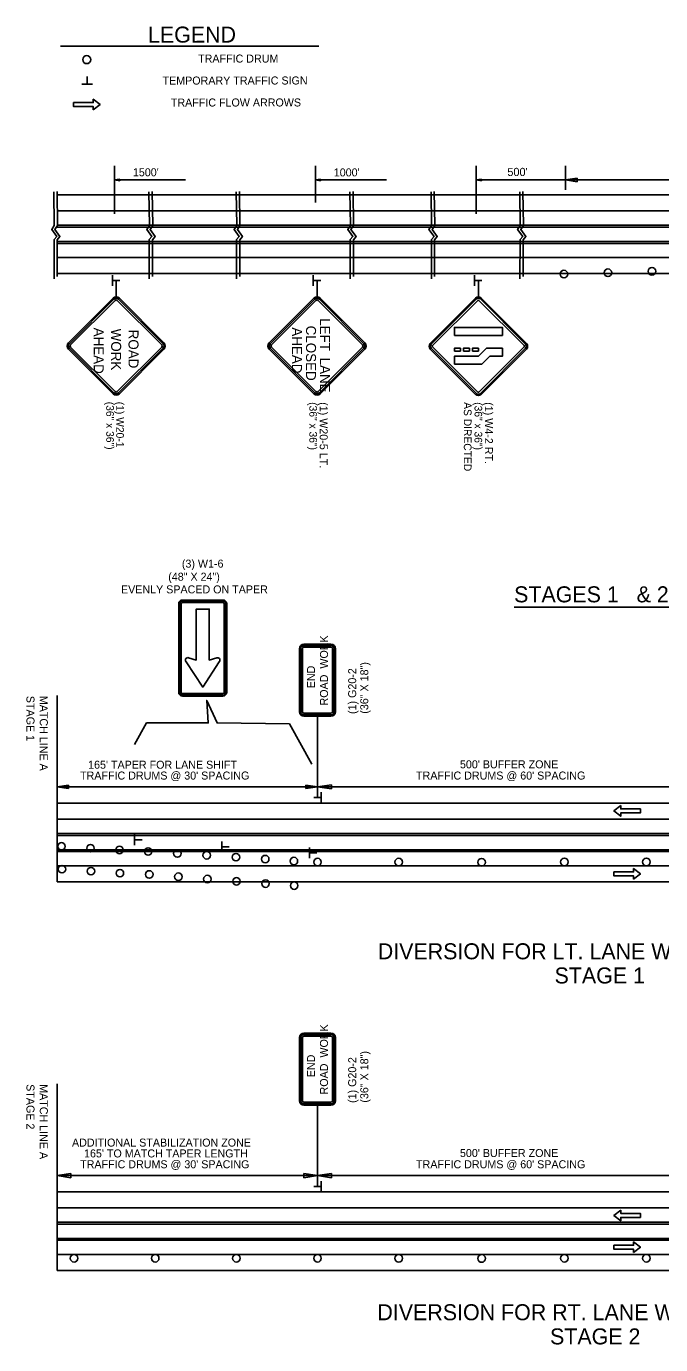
# Model space of a CAD drawing. Extents: x 1930579 to 1938445, y 596452 to 597630.
# Drawn here: x 1936470 to 1936946, y 596628 to 597617 of the extents above; entities that cross this region are included whole.
import ezdxf

# ---------------------------------------------------------------- set-up
doc = ezdxf.new("R2010")
doc.units = 0
for name, color, linetype in [('Default', 7, 'Continuous'), ('P_TC_Signs_Permanent', 7, 'Continuous'), ('P_TC_Signs_Temporary', 7, 'Continuous'), ('R_Border', 7, 'Continuous'), ('R_MOT', 7, 'Continuous'), ('R_Striping', 7, 'Continuous')]:
    doc.layers.add(name, color=color, linetype=linetype)

msp = doc.modelspace()

# ---------------------------------------------------------------- linework, layer by layer
at = {"layer": 'Default'}
for p, q in [((1936536.26, 597511.96), (1936536.26, 597476.04)), ((1936686.9, 597511.96), (1936686.9, 597484.57)), ((1936807.47, 597511.96), (1936807.47, 597476.04)), ((1936874.25, 597511.96), (1936874.25, 597493.95)), ((1936540.09, 597502), (1936536.26, 597501.43)), ((1936536.26, 597501.43), (1936589.49, 597501.43)), ((1936540.09, 597500.85), (1936536.26, 597501.43)), ((1936540.09, 597501.91), (1936536.9, 597501.43)), ((1936540.09, 597500.95), (1936536.9, 597501.43)), ((1936540.09, 597501.81), (1936537.56, 597501.43)), ((1936540.09, 597501.05), (1936537.56, 597501.43)), ((1936540.09, 597501.71), (1936538.2, 597501.43)), ((1936540.09, 597501.14), (1936538.2, 597501.43)), ((1936540.09, 597501.62), (1936538.84, 597501.43)), ((1936540.09, 597501.24), (1936538.84, 597501.43)), ((1936540.09, 597501.52), (1936539.48, 597501.43)), ((1936540.09, 597501.34), (1936539.48, 597501.43)), ((1936540.09, 597500.85), (1936540.09, 597502)), ((1936690.72, 597502), (1936686.9, 597501.43)), ((1936686.9, 597501.43), (1936740.13, 597501.43)), ((1936690.72, 597500.85), (1936686.9, 597501.43)), ((1936690.72, 597501.91), (1936687.54, 597501.43)), ((1936690.72, 597500.95), (1936687.54, 597501.43)), ((1936690.72, 597501.81), (1936688.2, 597501.43)), ((1936690.72, 597501.05), (1936688.2, 597501.43)), ((1936690.72, 597501.71), (1936688.83, 597501.43)), ((1936690.72, 597501.14), (1936688.83, 597501.43)), ((1936690.72, 597501.62), (1936689.48, 597501.43)), ((1936690.72, 597501.24), (1936689.48, 597501.43)), ((1936690.72, 597501.52), (1936690.12, 597501.43)), ((1936690.72, 597501.34), (1936690.12, 597501.43)), ((1936690.72, 597500.85), (1936690.72, 597502)), ((1936811.29, 597502), (1936807.47, 597501.43)), ((1936807.47, 597501.43), (1936874.25, 597501.43)), ((1936811.29, 597500.85), (1936807.47, 597501.43)), ((1936811.29, 597501.91), (1936808.1, 597501.43)), ((1936811.29, 597500.95), (1936808.1, 597501.43)), ((1936811.29, 597501.81), (1936808.76, 597501.43)), ((1936811.29, 597501.05), (1936808.76, 597501.43)), ((1936811.29, 597501.71), (1936809.4, 597501.43)), ((1936811.29, 597501.14), (1936809.4, 597501.43)), ((1936811.29, 597501.62), (1936810.05, 597501.43)), ((1936811.29, 597501.24), (1936810.05, 597501.43)), ((1936811.29, 597501.52), (1936810.69, 597501.43)), ((1936811.29, 597501.34), (1936810.69, 597501.43)), ((1936811.29, 597500.85), (1936811.29, 597502)), ((1936874.25, 597501.43), (1936883.11, 597502.76)), ((1937241.46, 597501.43), (1936874.25, 597501.43)), ((1936883.11, 597500.1), (1936874.25, 597501.43)), ((1936883.11, 597502.76), (1936883.11, 597500.1)), ((1937493.2, 597490.19), (1936493.11, 597490.19)), ((1937493.2, 597478.19), (1936493.3, 597478.19)), ((1937493.2, 597466.02), (1936492.72, 597466.02)), ((1937493.2, 597467.4), (1936493.46, 597467.4)), ((1937493.2, 597455.23), (1936493.31, 597455.23)), ((1937493.2, 597453.85), (1936493.31, 597453.85)), ((1937493.2, 597443.19), (1936493.31, 597443.19)), ((1937493.2, 597431.19), (1936493.31, 597431.19)), ((1936534.64, 597422.09), (1936534.64, 597430.07)), ((1936534.76, 597426.06), (1936540.21, 597426.06)), ((1936685.22, 597422.09), (1936685.22, 597430.07)), ((1936685.34, 597426.06), (1936690.79, 597426.06)), ((1936806.18, 597422.09), (1936806.18, 597430.07)), ((1936806.3, 597426.05), (1936811.75, 597426.05)), ((1936835.84, 597181.22), (1936964.15, 597181.22)), ((1936493.11, 597114.97), (1936493.11, 596975.31)), ((1936493.11, 597046.45), (1936501.81, 597047.75)), ((1936688.44, 597046.45), (1936493.11, 597046.45)), ((1936501.81, 597045.15), (1936493.11, 597046.45)), ((1936501.81, 597047.75), (1936501.81, 597045.15)), ((1936679.75, 597045.15), (1936679.75, 597047.75)), ((1936679.75, 597047.75), (1936688.44, 597046.45)), ((1936688.44, 597046.45), (1936679.75, 597045.15)), ((1936691.12, 597038.47), (1936685.67, 597038.47)), ((1936997.05, 597046.45), (1936688.44, 597046.45)), ((1936688.53, 597046.45), (1936698.83, 597048)), ((1936698.83, 597044.9), (1936688.53, 597046.45)), ((1936691.23, 597042.43), (1936691.23, 597034.45)), ((1936698.83, 597048), (1936698.83, 597044.9)), ((1937498.74, 597034.31), (1936493.11, 597034.31)), ((1936493.11, 597022.31), (1937498.74, 597022.31)), ((1937498.74, 597011.52), (1936493.11, 597011.52)), ((1937498.74, 597010.14), (1936493.11, 597010.14)), ((1936551.31, 597002.87), (1936551.31, 597010.85)), ((1937498.74, 596999.34), (1936493.11, 596999.34)), ((1936551.43, 597006.84), (1936556.87, 597006.84)), ((1936616.72, 596997.46), (1936616.72, 597005.44)), ((1936616.84, 597001.42), (1936622.29, 597001.42)), ((1936682.29, 596992.94), (1936682.29, 597000.92)), ((1937498.74, 596998.03), (1936493.11, 596998.03)), ((1936682.4, 596996.91), (1936687.85, 596996.91)), ((1936493.11, 596987.31), (1937498.74, 596987.31)), ((1936493.11, 596975.31), (1936773.63, 596975.31)), ((1937498.74, 596975.31), (1936493.11, 596975.31)), ((1936757.75, 596975.31), (1937032.82, 596975.31)), ((1936493.11, 596823.85), (1936493.11, 596683.94)), ((1936688.44, 596765.87), (1936688.44, 596749.76)), ((1936493.11, 596755.08), (1936503.42, 596756.63)), ((1936688.53, 596755.08), (1936493.11, 596755.08)), ((1936503.42, 596753.53), (1936493.11, 596755.08)), ((1936503.42, 596756.63), (1936503.42, 596753.53)), ((1936678.23, 596753.53), (1936678.23, 596756.63)), ((1936678.23, 596756.63), (1936688.53, 596755.08)), ((1936688.53, 596755.08), (1936678.23, 596753.53)), ((1936997.05, 596755.08), (1936688.44, 596755.08)), ((1936688.53, 596755.08), (1936698.83, 596756.63)), ((1936698.83, 596753.53), (1936688.53, 596755.08)), ((1936698.83, 596756.63), (1936698.83, 596753.53)), ((1937498.74, 596742.94), (1936493.11, 596742.94)), ((1936691.12, 596746.92), (1936685.67, 596746.92)), ((1936691.23, 596750.89), (1936691.23, 596742.91)), ((1936493.11, 596730.94), (1937498.74, 596730.94)), ((1937498.74, 596720.15), (1936493.11, 596720.15)), ((1937498.74, 596718.77), (1936493.11, 596718.77)), ((1937498.74, 596707.98), (1936493.11, 596707.98)), ((1937498.74, 596706.66), (1936493.11, 596706.66)), ((1936493.11, 596695.94), (1937498.74, 596695.94)), ((1937498.74, 596683.94), (1936493.11, 596683.94)), ((1936688.44, 596683.94), (1936773.63, 596683.94)), ((1936757.75, 596683.94), (1937032.82, 596683.94))]:
    msp.add_line(p, q, dxfattribs=at)
for points in [[(1936490.68, 597492.48), (1936491.07, 597467.24), (1936489.12, 597464.34), (1936492.91, 597459.14), (1936490.92, 597456.74), (1936490.91, 597427.4)], [(1936493.08, 597492.71), (1936493.46, 597467.14), (1936491.52, 597464.24), (1936495.31, 597459.04), (1936493.31, 597456.64), (1936493.31, 597429.08)], [(1936562.05, 597492.48), (1936562.43, 597467.24), (1936560.48, 597464.34), (1936564.28, 597459.14), (1936562.28, 597456.74), (1936562.27, 597427.4)], [(1936564.44, 597492.71), (1936564.83, 597467.14), (1936562.88, 597464.24), (1936566.68, 597459.04), (1936564.68, 597456.64), (1936564.67, 597429.08)], [(1936627.49, 597492.48), (1936627.87, 597467.24), (1936625.92, 597464.34), (1936629.72, 597459.14), (1936627.72, 597456.74), (1936627.72, 597427.4)], [(1936629.88, 597492.71), (1936630.27, 597467.14), (1936628.32, 597464.24), (1936632.12, 597459.04), (1936630.12, 597456.64), (1936630.12, 597429.08)], [(1936712.68, 597492.48), (1936713.07, 597467.24), (1936711.12, 597464.34), (1936714.91, 597459.14), (1936712.92, 597456.74), (1936712.91, 597427.4)], [(1936715.08, 597492.71), (1936715.46, 597467.14), (1936713.52, 597464.24), (1936717.31, 597459.04), (1936715.31, 597456.64), (1936715.31, 597429.08)], [(1936773.57, 597492.48), (1936773.95, 597467.24), (1936772, 597464.34), (1936775.8, 597459.14), (1936773.8, 597456.74), (1936773.79, 597427.4)], [(1936775.96, 597492.71), (1936776.35, 597467.14), (1936774.4, 597464.24), (1936778.2, 597459.04), (1936776.2, 597456.64), (1936776.19, 597429.08)], [(1936840.02, 597492.48), (1936840.41, 597467.24), (1936838.46, 597464.34), (1936842.26, 597459.14), (1936840.26, 597456.74), (1936840.25, 597427.4)], [(1936842.42, 597492.71), (1936842.8, 597467.14), (1936840.86, 597464.24), (1936844.65, 597459.04), (1936842.65, 597456.64), (1936842.65, 597429.08)]]:
    msp.add_lwpolyline(points, dxfattribs=at)
for centre, radius in [((1936515.36, 597591.57), 3), ((1936873.17, 597430.82), 2.87), ((1936906.15, 597431.86), 2.87), ((1936939.14, 597432.91), 2.87), ((1936496.43, 597001.89), 2.81), ((1936518.18, 597000.54), 2.81), ((1936539.92, 596999.19), 2.81), ((1936561.41, 596998), 2.81), ((1936583.36, 596996.58), 2.81), ((1936605.32, 596995.17), 2.81), ((1936627.27, 596993.75), 2.81), ((1936649.22, 596992.34), 2.81), ((1936670.72, 596990.86), 2.81), ((1936688.44, 596990.1), 2.81), ((1936749.3, 596990.1), 2.87), ((1936811.44, 596989.95), 2.87), ((1936873.58, 596990.16), 2.87), ((1936935.06, 596990.17), 2.87), ((1936496.8, 596984.78), 2.81), ((1936518.53, 596983.27), 2.81), ((1936540.25, 596981.76), 2.81), ((1936562.28, 596980.82), 2.81), ((1936584.07, 596979.1), 2.81), ((1936605.86, 596977.39), 2.81), ((1936627.65, 596975.67), 2.81), ((1936649.45, 596973.95), 2.81), ((1936670.92, 596972.45), 2.81), ((1936505.88, 596693.1), 2.81), ((1936566.73, 596693.1), 2.81), ((1936627.59, 596693.1), 2.81), ((1936688.44, 596693.1), 2.81), ((1936749.3, 596693.1), 2.87), ((1936811.44, 596692.96), 2.87), ((1936873.58, 596693.16), 2.87), ((1936935.06, 596693.18), 2.87)]:
    msp.add_circle(centre, radius, dxfattribs=at)
at = {"layer": 'P_TC_Signs_Permanent'}
for p, q in [((1936772.96, 597378.89), (1936806.9, 597412.83)), ((1936827.02, 597384.81), (1936827.02, 597390.81)), ((1936806.9, 597340.7), (1936772.96, 597374.65)), ((1936845.09, 597374.65), (1936811.15, 597340.7)), ((1936584.33, 597183.71), (1936584.33, 597117.33)), ((1936585.08, 597183.71), (1936585.08, 597117.33)), ((1936586.2, 597183.71), (1936586.2, 597117.33)), ((1936617.51, 597186.52), (1936587.14, 597186.52)), ((1936617.51, 597185.77), (1936587.14, 597185.77)), ((1936617.51, 597184.65), (1936587.14, 597184.65)), ((1936618.45, 597117.33), (1936618.45, 597183.71)), ((1936619.58, 597117.33), (1936619.58, 597183.71)), ((1936620.33, 597117.33), (1936620.33, 597183.71)), ((1936587.14, 597116.4), (1936617.51, 597116.4)), ((1936587.14, 597115.27), (1936617.51, 597115.27)), ((1936587.14, 597114.52), (1936617.51, 597114.52))]:
    msp.add_line(p, q, dxfattribs=at)
for points in [[(1936807.54, 597412.19), (1936773.6, 597378.25)], [(1936774.66, 597377.19), (1936808.6, 597411.13)], [(1936809.45, 597411.13), (1936843.39, 597377.19)], [(1936844.45, 597378.25), (1936810.51, 597412.19)], [(1936811.15, 597412.83), (1936828.12, 597395.86), (1936845.09, 597378.89)], [(1936773.6, 597375.28), (1936807.54, 597341.34)], [(1936808.6, 597342.4), (1936774.66, 597376.34)], [(1936843.39, 597376.34), (1936809.45, 597342.4)], [(1936810.51, 597341.34), (1936844.45, 597375.28)], [(1936612.96, 597143.22), (1936607.2, 597141.5), (1936607.2, 597179.77), (1936597.45, 597179.77), (1936597.45, 597141.5), (1936591.7, 597143.26)], [(1936589.88, 597140.26), (1936602.33, 597121.27), (1936614.73, 597140.27)]]:
    msp.add_lwpolyline(points, dxfattribs=at)
for points in [[(1936791.02, 597384.81), (1936791.02, 597390.81), (1936827.02, 597390.81), (1936827.02, 597384.81)], [(1936791.02, 597373.17), (1936791.02, 597375.27), (1936795.52, 597375.27), (1936795.52, 597373.17)], [(1936791.02, 597363.27), (1936791.02, 597369.27), (1936809.02, 597369.27), (1936815.02, 597375.27), (1936827.02, 597375.27), (1936827.02, 597369.27), (1936817.51, 597369.27), (1936811.51, 597363.27)], [(1936797.77, 597373.17), (1936797.77, 597375.27), (1936802.27, 597375.27), (1936802.27, 597373.17)], [(1936804.52, 597373.17), (1936804.52, 597375.27), (1936809.02, 597375.27), (1936809.02, 597373.17)]]:
    msp.add_lwpolyline(points, close=True, dxfattribs=at)
for centre, radius, start, end in [((1936809.02, 597410.71), 3, 45, 135), ((1936809.02, 597410.71), 2.1, 45, 135), ((1936809.02, 597410.71), 0.6, 45, 135), ((1936775.08, 597376.77), 3, 135, 225), ((1936775.08, 597376.77), 2.1, 135, 225), ((1936775.08, 597376.77), 0.6, 135, 225), ((1936842.97, 597376.77), 0.6, 315, 45), ((1936842.97, 597376.77), 2.1, 315, 45), ((1936842.97, 597376.77), 3, 315, 45), ((1936809.02, 597342.83), 3, 225, 315), ((1936809.02, 597342.83), 2.1, 225, 315), ((1936809.02, 597342.83), 0.6, 225, 315), ((1936587.14, 597183.71), 2.81, 90, 180), ((1936587.14, 597183.71), 2.06, 90, 180), ((1936587.14, 597183.71), 0.938, 90, 180), ((1936617.51, 597183.71), 2.81, 360, 90), ((1936617.51, 597183.71), 2.06, 360, 90), ((1936617.51, 597183.71), 0.937, 360, 90), ((1936591.21, 597141.53), 1.8, 74.03093, 213.47548), ((1936527.15, 597099.16), 75, 33.2286, 33.47548), ((1936613.44, 597141.53), 1.76, 326.59943, 105.96908), ((1936677.53, 597099.27), 75, 146.59943, 146.85697), ((1936587.14, 597117.33), 2.81, 180, 270), ((1936587.14, 597117.33), 2.06, 180, 270), ((1936587.14, 597117.33), 0.938, 180, 270), ((1936617.51, 597117.33), 2.81, 270, 360), ((1936617.51, 597117.33), 2.06, 270, 360), ((1936617.51, 597117.33), 0.938, 270, 360)]:
    msp.add_arc(centre, radius, start, end, dxfattribs=at)
at = {"layer": 'P_TC_Signs_Temporary'}
for p, q in [((1936501.69, 597379.31), (1936535.1, 597412.72)), ((1936502.35, 597378.65), (1936535.76, 597412.06)), ((1936503.28, 597377.72), (1936536.69, 597411.13)), ((1936538.28, 597411.13), (1936571.69, 597377.72)), ((1936539.21, 597412.06), (1936572.62, 597378.65)), ((1936539.87, 597412.72), (1936573.28, 597379.31)), ((1936652.27, 597379.31), (1936685.68, 597412.72)), ((1936652.93, 597378.65), (1936686.34, 597412.06)), ((1936653.86, 597377.72), (1936687.27, 597411.13)), ((1936688.86, 597411.13), (1936722.27, 597377.72)), ((1936689.79, 597412.06), (1936723.2, 597378.65)), ((1936690.45, 597412.72), (1936723.86, 597379.31)), ((1936535.1, 597341.12), (1936501.69, 597374.54)), ((1936535.76, 597341.79), (1936502.35, 597375.2)), ((1936536.69, 597342.72), (1936503.28, 597376.13)), ((1936571.69, 597376.13), (1936538.28, 597342.72)), ((1936572.62, 597375.2), (1936539.21, 597341.79)), ((1936573.28, 597374.54), (1936539.87, 597341.12)), ((1936685.68, 597341.12), (1936652.27, 597374.54)), ((1936686.34, 597341.79), (1936652.93, 597375.2)), ((1936687.27, 597342.72), (1936653.86, 597376.13)), ((1936722.27, 597376.13), (1936688.86, 597342.72)), ((1936723.2, 597375.2), (1936689.79, 597341.79)), ((1936723.86, 597374.54), (1936690.45, 597341.12)), ((1936674.89, 597150.04), (1936674.89, 597102.79)), ((1936675.83, 597150.04), (1936675.83, 597102.79)), ((1936677.14, 597150.04), (1936677.14, 597102.79)), ((1936698.52, 597153.42), (1936678.27, 597153.42)), ((1936698.52, 597152.48), (1936678.27, 597152.48)), ((1936698.52, 597151.17), (1936678.27, 597151.17)), ((1936699.64, 597102.79), (1936699.64, 597150.04)), ((1936700.96, 597102.79), (1936700.96, 597150.04)), ((1936701.89, 597102.79), (1936701.89, 597150.04)), ((1936678.27, 597101.67), (1936698.52, 597101.67)), ((1936678.27, 597100.36), (1936698.52, 597100.36)), ((1936678.27, 597099.42), (1936698.52, 597099.42)), ((1936698.52, 596861.87), (1936678.27, 596861.87)), ((1936698.52, 596860.93), (1936678.27, 596860.93)), ((1936674.89, 596858.5), (1936674.89, 596811.25)), ((1936675.83, 596858.5), (1936675.83, 596811.25)), ((1936677.14, 596858.5), (1936677.14, 596811.25)), ((1936698.52, 596859.62), (1936678.27, 596859.62)), ((1936699.64, 596811.25), (1936699.64, 596858.5)), ((1936700.96, 596811.25), (1936700.96, 596858.5)), ((1936701.89, 596811.25), (1936701.89, 596858.5)), ((1936678.27, 596810.12), (1936698.52, 596810.12)), ((1936678.27, 596808.81), (1936698.52, 596808.81)), ((1936678.27, 596807.87), (1936698.52, 596807.87))]:
    msp.add_line(p, q, dxfattribs=at)
for centre, radius, start, end in [((1936537.49, 597410.33), 3.38, 45, 135), ((1936537.49, 597410.33), 2.44, 45, 135), ((1936537.49, 597410.33), 1.12, 45, 135), ((1936688.06, 597410.33), 3.38, 45, 135), ((1936688.06, 597410.33), 2.44, 45, 135), ((1936688.06, 597410.33), 1.12, 45, 135), ((1936504.07, 597376.92), 3.38, 135, 225), ((1936504.07, 597376.92), 2.44, 135, 225), ((1936504.07, 597376.92), 1.13, 135, 225), ((1936570.9, 597376.92), 1.13, 315, 45), ((1936570.9, 597376.92), 2.44, 315, 45), ((1936570.9, 597376.92), 3.38, 315, 45), ((1936654.65, 597376.92), 3.38, 135, 225), ((1936654.65, 597376.92), 2.44, 135, 225), ((1936654.65, 597376.92), 1.13, 135, 225), ((1936721.47, 597376.92), 1.13, 315, 45), ((1936721.47, 597376.92), 2.44, 315, 45), ((1936721.47, 597376.92), 3.38, 315, 45), ((1936537.49, 597343.51), 3.38, 225, 315), ((1936537.49, 597343.51), 2.44, 225, 315), ((1936537.49, 597343.51), 1.12, 225, 315), ((1936688.06, 597343.51), 3.38, 225, 315), ((1936688.06, 597343.51), 2.44, 225, 315), ((1936688.06, 597343.51), 1.12, 225, 315), ((1936678.27, 597150.04), 3.38, 90, 180), ((1936678.27, 597150.04), 2.44, 90, 180), ((1936678.27, 597150.04), 1.13, 90, 180), ((1936698.52, 597150.04), 3.38, 360, 90), ((1936698.52, 597150.04), 2.44, 360, 90), ((1936698.52, 597150.04), 1.13, 360, 90), ((1936678.27, 597102.79), 3.38, 180, 270), ((1936678.27, 597102.79), 2.44, 180, 270), ((1936678.27, 597102.79), 1.13, 180, 270), ((1936698.52, 597102.79), 2.44, 270, 360), ((1936698.52, 597102.79), 1.13, 270, 360), ((1936698.52, 597102.79), 3.38, 270, 360), ((1936678.27, 596858.5), 3.38, 90, 180), ((1936678.27, 596858.5), 2.44, 90, 180), ((1936698.52, 596858.5), 3.38, 360, 90), ((1936698.52, 596858.5), 2.44, 360, 90), ((1936678.27, 596858.5), 1.13, 90, 180), ((1936698.52, 596858.5), 1.13, 360, 90), ((1936678.27, 596811.25), 3.38, 180, 270), ((1936678.27, 596811.25), 2.44, 180, 270), ((1936678.27, 596811.25), 1.13, 180, 270), ((1936698.52, 596811.25), 2.44, 270, 360), ((1936698.52, 596811.25), 1.13, 270, 360), ((1936698.52, 596811.25), 3.38, 270, 360)]:
    msp.add_arc(centre, radius, start, end, dxfattribs=at)
at = {"layer": 'R_Border'}
for p, q in [((1936495.59, 597601.6), (1936689.5, 597601.73)), ((1936519.72, 597573.29), (1936511.72, 597573.28)), ((1936515.74, 597573.4), (1936515.74, 597578.86)), ((1936537.49, 597426.06), (1936537.49, 597413.71)), ((1936688.06, 597426.06), (1936688.06, 597413.71)), ((1936809.02, 597426.05), (1936809.02, 597413.71)), ((1936688.39, 597099.42), (1936688.39, 597038.47)), ((1936688.39, 596807.87), (1936688.39, 596746.92))]:
    msp.add_line(p, q, dxfattribs=at)
msp.add_lwpolyline([(1936551.31, 597078.12), (1936560.31, 597094.42), (1936606.55, 597094.42), (1936605.35, 597111.31), (1936613.15, 597094.42), (1936667.35, 597093.63), (1936684.23, 597063.48)], dxfattribs=at)
at = {"layer": 'R_MOT'}
msp.add_lwpolyline([(1936520.24, 597553.89), (1936525.43, 597557.89), (1936520.23, 597561.89), (1936520.23, 597559.39), (1936505.52, 597559.38), (1936505.52, 597556.38), (1936520.24, 597556.39)], close=True, dxfattribs=at)
at = {"layer": 'R_Striping'}
for points in [[(1936915.85, 597032.39), (1936910.66, 597028.39), (1936915.85, 597024.39), (1936915.85, 597026.89), (1936930.56, 597026.89), (1936930.56, 597029.89), (1936915.85, 597029.89)], [(1936925.37, 596977.26), (1936930.56, 596981.26), (1936925.37, 596985.26), (1936925.37, 596982.76), (1936910.66, 596982.76), (1936910.66, 596979.76), (1936925.37, 596979.76)], [(1936915.85, 596729.24), (1936910.66, 596725.24), (1936915.85, 596721.24), (1936915.85, 596723.74), (1936930.56, 596723.74), (1936930.56, 596726.74), (1936915.85, 596726.74)], [(1936925.37, 596697.41), (1936930.56, 596701.41), (1936925.37, 596705.41), (1936925.37, 596702.91), (1936910.66, 596702.91), (1936910.66, 596699.91), (1936925.37, 596699.91)]]:
    msp.add_lwpolyline(points, close=True, dxfattribs=at)

# ---------------------------------------------------------------- texts
at = {"layer": 'Default'}
for s, height, rotation, p in [("1500'", 6, 360, (1936549.98, 597504.15)), ("1000'", 6, 360, (1936700.62, 597504.06)), ("500'", 6.12, 360, (1936830.76, 597504.34)), ('STAGES 1   & 2', 12, 360, (1936835.84, 597184.79)), ('STAGE 1', 6, 270, (1936470.18, 597114.71)), ('MATCH LINE A ', 6, 270, (1936480.18, 597114.71)), ("TRAFFIC DRUMS @ 30' SPACING", 6, 360, (1936510.37, 597051.95)), ("165' TAPER FOR LANE SHIFT", 6, 360, (1936516.4, 597060.08)), ("TRAFFIC DRUMS @ 60' SPACING", 6, 360, (1936762.31, 597051.95)), ("500' BUFFER ZONE", 6, 360, (1936795.24, 597060.38)), ('DIVERSION FOR LT. LANE WORK ZONE', 12, 360, (1936733.6, 596917.22)), ('STAGE 1', 12, 360, (1936866.17, 596899.1)), ('STAGE 2', 6, 270, (1936470.18, 596823.6)), ('MATCH LINE A ', 6, 270, (1936480.18, 596823.6)), ('ADDITIONAL STABILIZATION ZONE', 6, 360, (1936504.32, 596776.83)), ("165' TO MATCH TAPER LENGTH", 6, 360, (1936513.36, 596768.71)), ("500' BUFFER ZONE", 6, 360, (1936795.24, 596769.01)), ("TRAFFIC DRUMS @ 30' SPACING", 6, 360, (1936510.44, 596760.58)), ("TRAFFIC DRUMS @ 60' SPACING", 6, 360, (1936762.31, 596760.58)), ('DIVERSION FOR RT. LANE WORK ZONE', 12, 360, (1936733.32, 596646.67)), ('STAGE 2', 12, 360, (1936862.77, 596628.55))]:
    msp.add_text(s, height=height, rotation=rotation, dxfattribs=at).set_placement(p)
at = {"layer": 'P_TC_Signs_Temporary'}
for s, height, rotation, p in [('LEFT\u2002LANE', 7.5, 270, (1936690.31, 597397.72)), (' AHEAD ', 7.5, 270, (1936520.65, 597393.46)), ('WORK', 7.5, 270, (1936533.68, 597389.91)), (' ROAD ', 7.5, 270, (1936546.7, 597391.94)), (' AHEAD ', 7.5, 270, (1936669.31, 597393.69)), ('CLOSED', 7.5, 270, (1936679.81, 597392.17)), ('ROAD  WORK', 6, 90, (1936696.27, 597107.46)), ('END', 6, 90, (1936686.52, 597120.39)), ('ROAD  WORK', 6, 90, (1936696.27, 596815.91)), ('END', 6, 90, (1936686.52, 596828.84))]:
    msp.add_text(s, height=height, rotation=rotation, dxfattribs=at).set_placement(p)
at = {"layer": 'R_Border'}
for s, height, rotation, p in [('LEGEND', 12, 0.03878, (1936561.32, 597604.33)), ('TRAFFIC DRUM', 6, 0.03876, (1936598.9, 597589.37)), ('TEMPORARY TRAFFIC SIGN', 6, 0.03876, (1936572.23, 597572.89)), ('TRAFFIC FLOW ARROWS', 6, 0.03876, (1936578.44, 597556.43)), ('AS DIRECTED ', 5.76, 270, (1936798.14, 597334.83)), ('(36" x 36")', 5.76, 270, (1936530, 597335.14)), ('(1) W20-1', 5.76, 270, (1936537.49, 597335.14)), ('(36" x 36")', 5.76, 270, (1936682.3, 597334.83)), ('(1) W20-5 LT.', 6, 270, (1936690.07, 597334.83)), ('(36" x 36")', 5.76, 270, (1936806.14, 597334.83)), ('(1) W4-2 RT.', 6, 270, (1936813.91, 597334.83)), ('(3) W1-6', 6, 0.00754, (1936586.71, 597210.8)), ('(48" X 24")', 6, 0.00754, (1936576.48, 597201)), ('EVENLY SPACED ON TAPER', 6, 0.00754, (1936541.07, 597191.5)), ('(36" X 18")', 6, 90, (1936726.48, 597101.31)), ('(1) G20-2', 6, 90, (1936717.43, 597101.1)), ('(1) G20-2', 6, 90, (1936717.43, 596809.55)), ('(36" X 18")', 6, 90, (1936726.48, 596809.77))]:
    msp.add_text(s, height=height, rotation=rotation, dxfattribs=at).set_placement(p)

doc.saveas('drawing.dxf')
